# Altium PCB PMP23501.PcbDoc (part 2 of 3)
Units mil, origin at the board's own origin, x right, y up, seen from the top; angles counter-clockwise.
Board outline 4950 x 3450 mil, 4 copper layers (Top Layer, Layer 1, Layer 2, Bottom Layer), stack 70.356 mil thick; 186 components, 84 nets, 554 pads, 643 vias.
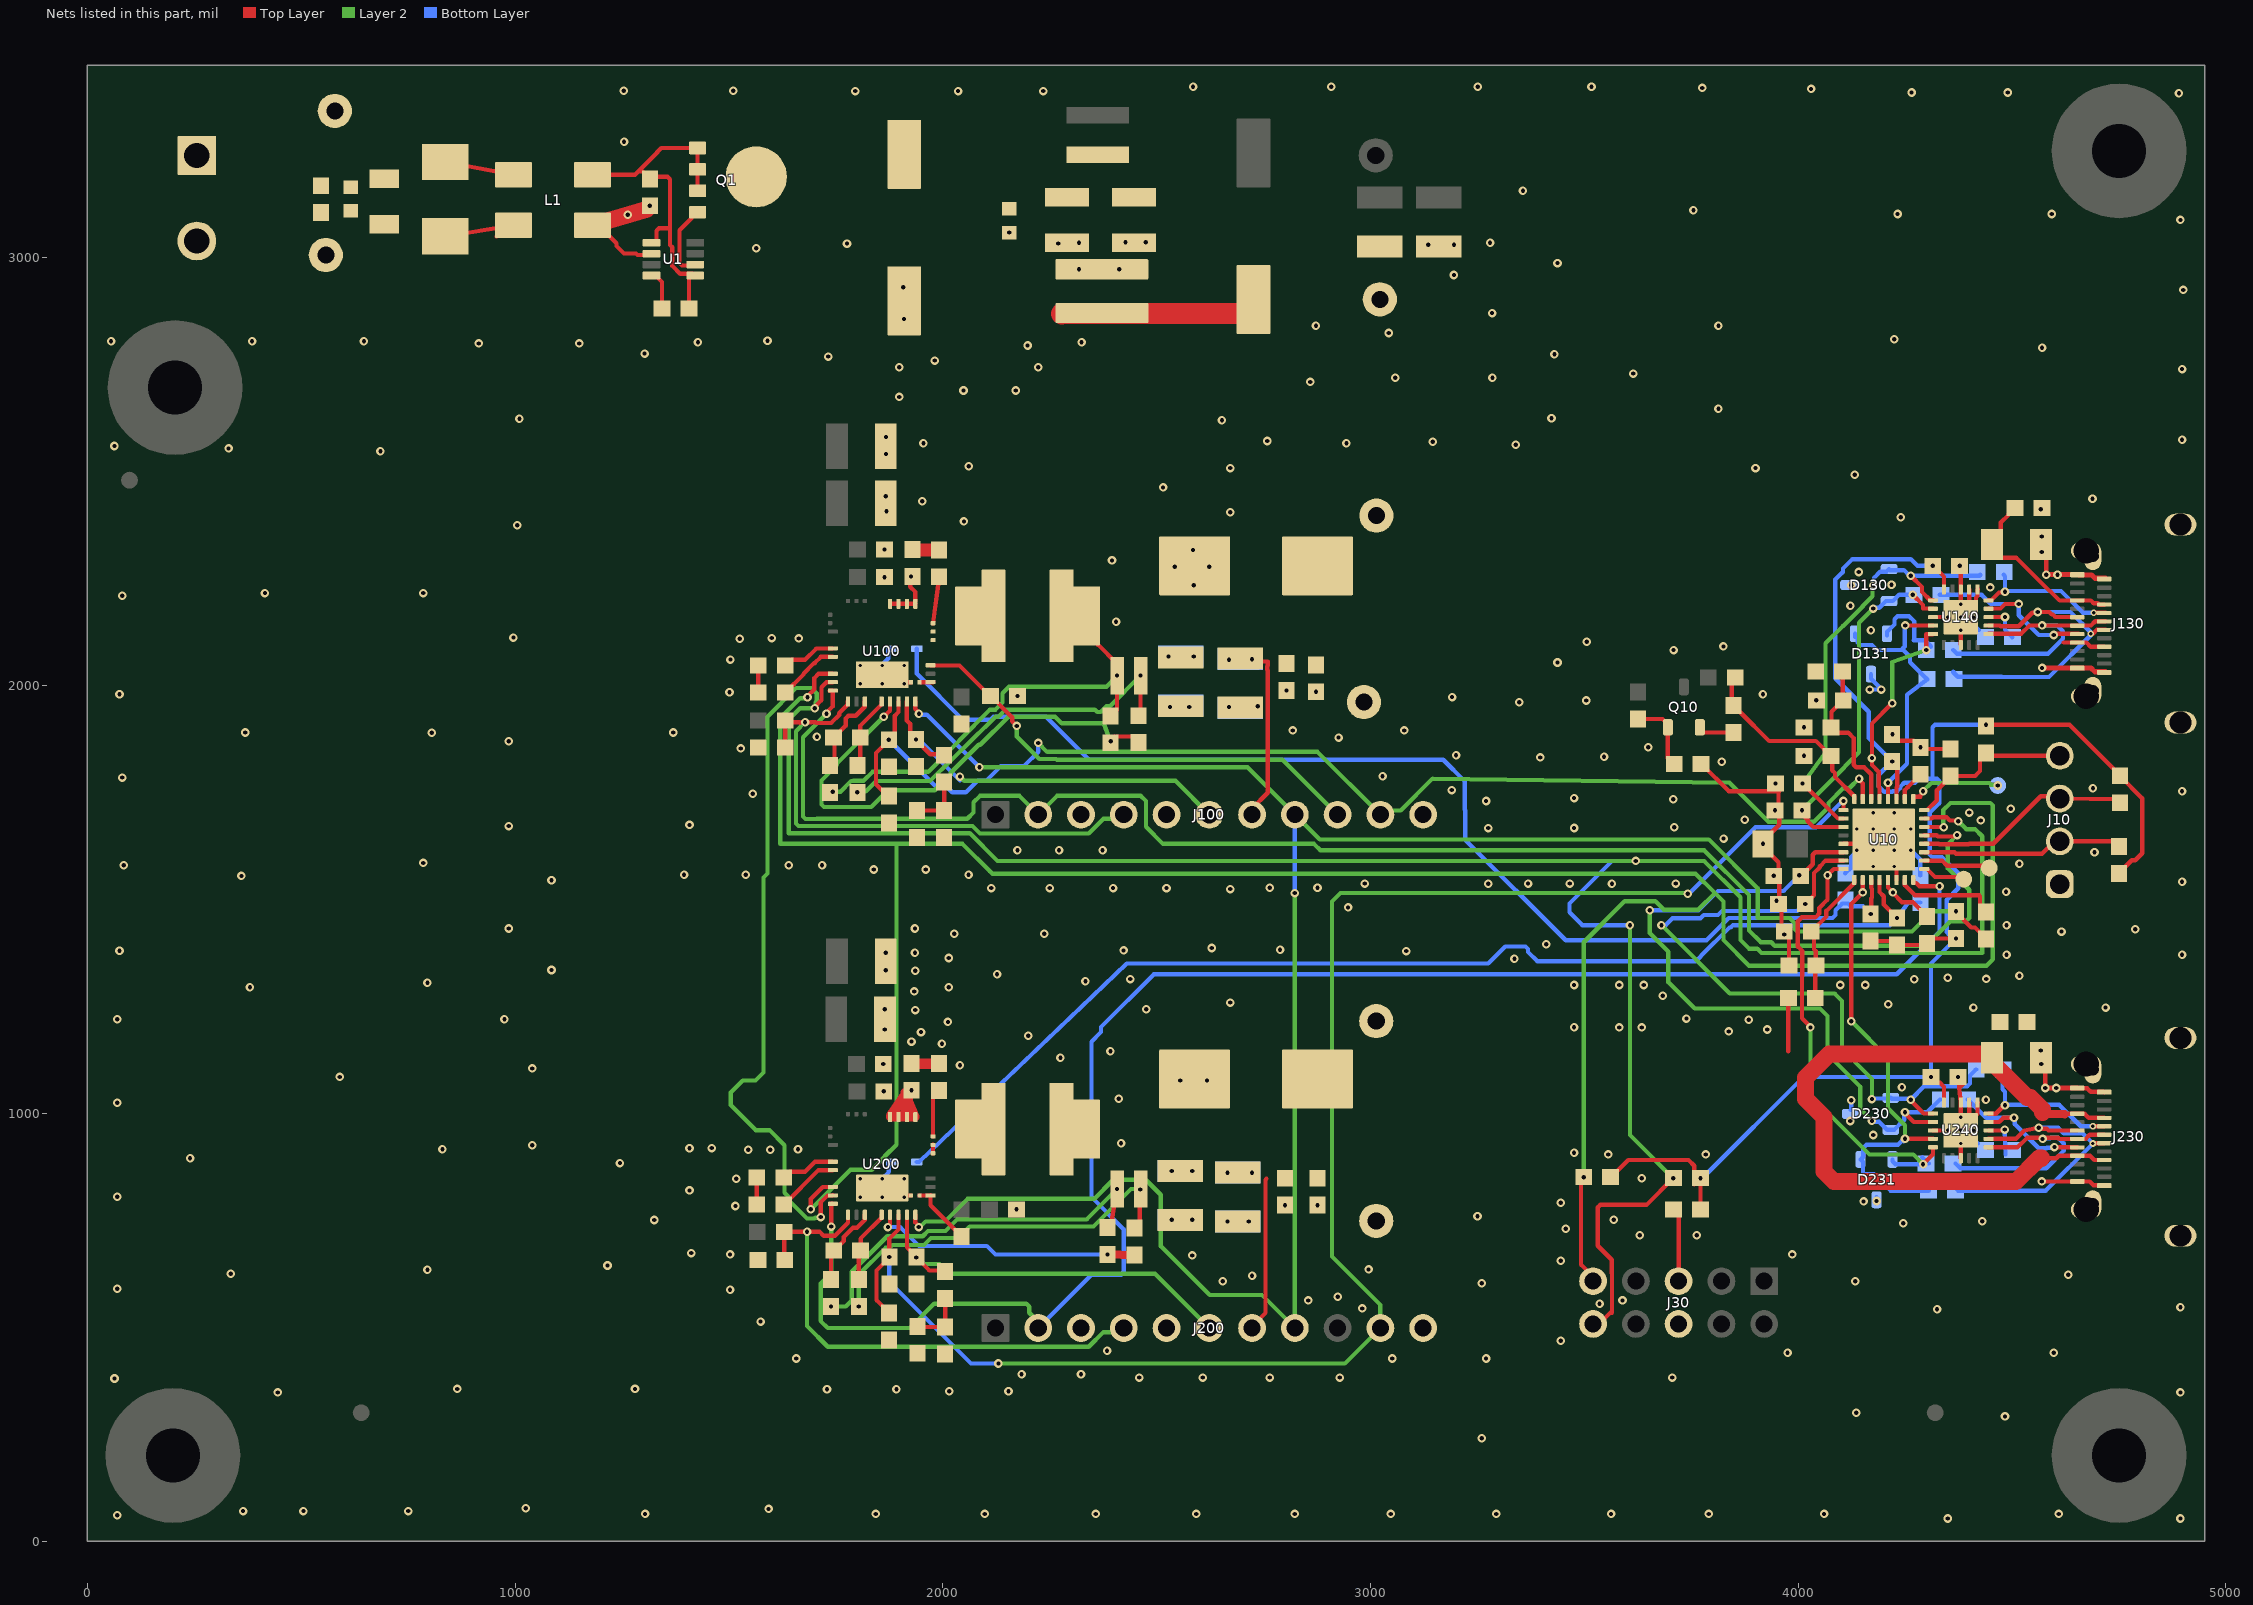
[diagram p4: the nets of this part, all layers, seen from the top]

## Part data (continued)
R106 R108 R112 R135 R136 R137 R138 R206 R208 R212 R235 R236 R237 R238: library part CMP-0025885-5, "RES, 0, 5%, 0.1 W, 0603", Manufacturer=Yageo, Power_W=100mW, Supplier Part Number 1=311-0.0GRCT-ND, TempCo="200 ppm/C", Tolerance_%=5%, Value2=0.1W, Value_Code=0000, ValueDisplayed=0
R107 R207: library part CMP-0025825-4, "RES, 51, 5%, 0.1 W, AEC-Q200 Grade 0, 0603", Manufacturer=Vishay-Dale, Power_W=100mW, Supplier Part Number 1=541-51GCT-ND, TempCo="200 ppm/C", Tolerance_%=5%, Value2=0.1W, Value_Code=51R0, ValueDisplayed=51
R109 R209: library part CMP-0022302-4, "RES, 2.00, 1%, 0.1 W, AEC-Q200 Grade 0, 0603", Manufacturer=Vishay-Dale, PartNumber=CRCW06032R00FKEA, Power_W=100mW, Supplier Part Number 1=541-2.00HHCT-ND, TempCo="100 ppm/C", Tolerance_%=1%, Value2=0.1W, Value_Code=2R00, ValueDisplayed=2.00
R111 R211: library part CMP-0015103-2, "RES, 0.008, 1%, 1 W, AEC-Q200 Grade 0, 0508", Manufacturer="Susumu Co Ltd", Power_W=1W, TempCo="25 ppm/C", Tolerance_%=1%, Value_Code=8L000, ValueDisplayed=0.008
R113 R213: library part CMP-0025832-4, "RES, 5.1 M, 5%, 0.1 W, AEC-Q200 Grade 0, 0603", Manufacturer=Vishay-Dale, Power_W=100mW, Supplier Part Number 1=541-5.1MGCT-ND, TempCo="200 ppm/C", Tolerance_%=5%, Value2=0.1W, Value_Code=5M10, ValueDisplayed=5.1M
R204: library part CMP-0022494-4, "RES, 54.9 k, 1%, 0.1 W, AEC-Q200 Grade 0, 0603", Manufacturer=Vishay-Dale, Power_W=100mW, Supplier Part Number 1=541-54.9KHCT-ND, TempCo="100 ppm/C", Tolerance_%=1%, Value2=0.1W, Value_Code=54k9, ValueDisplayed=54.9k
TP1 TP3 TP100 TP200: library part CMP-0055137-2, "Test Point, Miniature, Red, TH", Color=Red, Manufacturer="Keystone Electronics", Supplier Part Number 1=36-5000-ND
TP2 TP4 TP101 TP201: library part CMP-0055138-2, "Test Point, Miniature, Black, TH", Color=Black, Manufacturer="Keystone Electronics", Supplier Part Number 1=36-5001-ND
TP10 TP11 TP12: library part CMP-0003825-1, "1mm Test Point, SMT", Manufacturer=Any
U1: library part CMP-0090679-1, "Low IQ Reverse Battery Protection Controller", Manufacturer="Texas Instruments", Max Supply Voltage=60V, Min Supply Voltage=4V, Nominal Supply Current=80uA, Operating Temperature Range="-40°C to +150°C"
U10: library part CMP-0122052-1, "Automotive Dual-Port USB Type-C® PD Controller with 240W EPR and DisplayPortTM over USB Type-C", Manufacturer="Texas Instruments", Max Supply Voltage=32V, Min Supply Voltage=4.5V, Operating Temperature Range="-40°C to +125°C"
U100 U200: library part CMP-0123531-1, "70V, 3A, Automotive, High Efficiency CC-CV Buck Converter with I2C", Manufacturer="Texas Instruments", Max Supply Voltage=70V, Min Supply Voltage=4.5V, Operating Temperature Range="-40°C to +150°C", Output Voltage=1-24V, Switching Frequency=200-2200kHz
U140 U240: library part CMP-0035132-1, "USB Type-C® 48V EPR Port Protector: Short-to-VBUS Overvoltage and IEC ESD Protection", Manufacturer="Texas Instruments", Operating Supply Voltage=3.3V, Operating Temperature Range="-40°C to +125°C"
ZZ1: library part CMP-0003616-3
ZZ2: library part CMP-0077236-1
ZZ3: library part CMP-0077237-1
ZZ4: library part CMP-0077238-1

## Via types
v1: diameter 20, hole 10, Top Layer to Bottom Layer, tented both sides, 592 vias
v2: diameter 19.68, hole 7.87, Top Layer to Bottom Layer, tented both sides, 46 vias
v3: diameter 16, hole 8, Top Layer to Bottom Layer, tented both sides, 4 vias
v4: diameter 20/20/20/20 (per signal layer), hole 10, Top Layer to Bottom Layer, tented bottom, 1 vias

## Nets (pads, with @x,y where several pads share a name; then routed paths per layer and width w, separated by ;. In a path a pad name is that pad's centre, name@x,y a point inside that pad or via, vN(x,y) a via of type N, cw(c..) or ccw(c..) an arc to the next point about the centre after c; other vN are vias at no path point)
3.3V: C19.2 C140.1 C240.1 R12.1 R16.2 R20.2 R21.2 R22.2 R27.2 R28.2 R30.2 R31.2 R32.2 U10.27 U140.10 U240.10 | length 4088.7
  Top Layer w10: R31.2@3561.35,850.51 3562.34,850.51 3602.69,890.87 3743.2,890.87 3756.81,877.25 3756.81,861.93 R30.2@3770.51,848.23 ; R30.2@3756.81,833.55 3756.81,834.53 R30.2@3770.51,848.23 ; R32.2@3771.5,774.92 v1(3771.5,848.23) R30.2@3770.51,848.23 ; R16.2@4169.29,1403 4221.19,1403 R21.2@4230.77,1393.41 4297.14,1393.41 R22.2@4300.73,1397 4312.23,1408.5 v1(4368.59,1408.5) ; v1(4219.65,1822.76) 4231.34,1811.07 4231.34,1764.12 4229.53,1762.31 U10.27@4229.53,1734.49 ; v1(4310.31,1085) 4324.02,1071.3 4331.14,1071.3 4340.63,1061.81 U240.10@4340.63,1024.96 ; v1(4314.28,2280.06) 4315.27,2280.06 4340.63,2254.7 U140.10@4340.63,2224.96 ; v1(4438.86,1908.46) 4634.22,1908.46 4752.43,1790.25 R28.2@4752.43,1789.27 4752.43,1788.28 4804.37,1736.35 4804.37,1607.95 4788.07,1591.65 4779.66,1591.65 4749.66,1561.65 R27.2@4749.66,1560.67
  Bottom Layer w10: v1(3771.5,848.23) 3771.5,849.22 3777.35,855.08 3782.36,855.08 4012.28,1085 v1(4310.31,1085) 4310.31,1350.23 v1(4368.59,1408.5) 4365.88,1408.5 4358.01,1416.38 4354.37,1416.38 4347.09,1423.66 4347.09,1499.03 4374.09,1526.04 4374.09,1561.5 4336.32,1599.27 4313.06,1599.27 4307.2,1605.13 4307.2,1701.97 4330.39,1725.16 4330.39,1776.64 4324.54,1782.5 4314.05,1782.5 ; v1@4312.37,2281.97 v1(4314.28,2280.06) 4278.63,2280.06 4262.98,2295.71 4126.44,2295.71 4104.5,2273.77 4104.5,2265.04 4103.5,2265.04 4086.57,2248.11 4086.57,2017.11 4164.78,1938.91 4164.78,1877.63 v1(4219.65,1822.76) 4188.34,1791.45 4188.34,1764.12 4200.94,1751.53 4219.63,1751.53 4221.29,1753.19 4231.12,1753.19 4238.85,1760.92 4238.85,1764.12 4247.76,1773.03 4272.97,1773.03 4282.44,1782.5 4314.05,1782.5 ; v1(4438.86,1908.46) 4319.91,1908.46 4314.05,1902.6 4314.05,1782.5
AGND_A: C100.2 C101.2 C102.2 C104.1 NT100.2 R100.1 R104.1 R113.1 U100.17 | length 31.4
  Top Layer w10: C102.2@1873.73,1820.27 C102.2@1873.73,1822.24 ; NT100.2@1948.15,2007.87 1970.75,2007.87 1977.48,2007.87 U100.17@1977.56,2007.8
AGND_B: C200.2 C201.2 C202.2 C204.1 NT200.2 R200.1 R204.1 R213.1 U200.17 | length 152
  Top Layer w10: NT200.2@1945.66,808.02 1971.09,808.02 U200.17@1971.17,808.1 1971.17,784.89 2043.5,712.57 C204.1@2043.5,711.58
CC1_A: C17.2 D130.2 R135.1 U10.3 U140.12 | length 832.3
  Top Layer w10: C17.2@3994.95,1697.11 C17.2@3996.92,1697.11 ; C17.2@4005.03,1702.99 4022.17,1685.85 4022.17,1682.38 4035.02,1669.53 U10.3@4105.51,1669.53 ; v1(4267.76,2212.29) 4291.72,2188.32 4291.72,2180.12 U140.12@4315.04,2180.12
  Layer 2 w10: v1(4008.74,1708.5) 4142.09,1843.99 4142.09,2147.01 v1(4175.2,2180.12)
  Bottom Layer w10: v1(4175.2,2180.12) 4177.11,2182.03 4189.31,2182.03 4204.88,2197.6 4213.24,2197.6 4221.13,2197.6 4235.82,2212.29 v1(4267.76,2212.29) R135.1@4270.5,2212.29
CC1_A_C: J130.A5 R135.2 U140.4 | length 458.2
  Top Layer w10: U140.4@4444.96,2180.12 4472.63,2180.12 4483.45,2190.94 v1(4515.68,2190.94) ; v1(4597.66,2118.25) 4600.37,2118.25 4603.19,2121.06 J130.A5@4655.51,2121.06
  Bottom Layer w10: R135.2@4330.75,2212.29 4428.8,2212.29 4450.14,2190.94 v1(4515.68,2190.94) 4515.68,2164.67 4562.1,2118.25 v1(4597.66,2118.25) v1@4600.37,2118.25
CC1_B: C18.1 D230.2 R235.1 U10.6 U240.12 | length 1685.3
  Top Layer w10: v1(4002.63,1556.79) 4008.48,1556.79 4033.98,1582.29 4033.98,1604.61 4039.84,1610.47 U10.6@4105.51,1610.47 ; v1(4249.61,1002.5) 4249.61,1000.16 4270.08,979.68 U240.12@4315.04,979.68
  Layer 2 w10: v1(3652.6,1474.59) 3652.6,1421.33 3696.3,1377.63 3696.3,1306.5 3757.8,1245 4050.78,1245 4068.5,1227.28 4068.5,1138.56 4145.2,1061.86 4145.2,1009.29 v1(4172.29,982.2)
  Bottom Layer w10: v1(3652.6,1474.59) 3766.92,1474.59 3812.33,1520 3965.84,1520 v1(4002.63,1556.79) ; v1(4172.29,982.2) 4174.2,980.29 4188.9,980.29 4207.89,961.3 D230.2@4216.25,961.3 4224.12,961.3 4247.69,984.87 4247.69,1000.59 v1(4249.61,1002.5) 4301.48,1002.5 4331.46,1032.48 R235.1@4332.44,1032.48
CC1_B_C: J230.A5 R235.2 U240.4 | length 377.6
  Top Layer w10: U240.4@4444.96,979.68 4469.78,979.68 4479.39,989.29 v1(4504.46,989.29) ; v1@4598.23,921.81 4599.65,920.39 J230.A5@4652.36,920.39
  Bottom Layer w10: R235.2@4395.43,1032.48 4396.42,1032.48 4439.61,989.29 v1(4504.46,989.29) 4506.37,987.38 4506.37,974.47 4562.34,918.5 4580.15,918.5 4580.84,919.19 4597.02,919.19 v1(4598.94,921.1)
CC2_A: C15.2 D130.1 R136.1 U10.2 U140.11 | length 1023.2
  Top Layer w10: v1(4009.69,1771.1) 4010.67,1771.1 4037.37,1744.4 4038.17,1744.4 4093.28,1689.29 4105.43,1689.29 U10.2@4105.51,1689.21 ; v1(4262.99,2256.63) 4289.26,2230.37 4289.26,2218.62 4308.5,2199.37 U140.11@4315.04,2199.37
  Layer 2 w10: v1@4010.93,1770.21 4063.81,1843.99 4063.81,2099.13 4103.22,2138.54 4104.09,2138.54 4150.59,2185.04 4150.59,2185.91 4173.54,2208.87 4173.54,2232.21 v1(4175.2,2233.87)
  Bottom Layer w10: v1(4175.2,2233.87) 4177.11,2235.78 4177.11,2251.93 4191.67,2266.5 4206.34,2266.5 D130.1@4212.24,2272.4 4214.65,2269.99 4246.93,2269.99 4260.29,2256.63 v1(4262.99,2256.63) 4423.92,2256.63 4425.24,2257.95 R136.1@4425.24,2258.94
CC2_A_C: J130.B5 R136.2 U140.5 | length 344.3
  Top Layer w10: U140.5@4444.96,2199.8 4451.5,2199.8 4469.27,2217.57 4481.43,2217.57 v1(4483.35,2219.49) ; v3(4690.8,2170.28) J130.B5@4718.5,2170.28
  Bottom Layer w10: R136.2@4480.36,2258.94 4483.35,2255.95 v1(4483.35,2219.49) 4485.16,2221.3 4614.33,2221.3 4665.35,2170.28 v3(4690.8,2170.28)
CC2_B: C16.1 D230.1 R236.1 U10.7 U240.11 | length 1617.8
  Top Layer w10: v1(4016.5,1489.31) 4017.48,1489.31 4031.18,1503.01 4031.18,1503.99 4036.99,1509.8 4036.99,1561.96 4050.48,1575.46 4050.48,1577.37 4063.9,1590.79 U10.7@4105.51,1590.79 ; v1(4262.99,1031.85) 4262.99,1029.92 4293.54,999.37 U240.11@4315.04,999.37
  Layer 2 w10: v1(3680,1440) 3840,1280 4085,1280 4102.2,1262.8 4102.2,1150.09 4172.29,1080 v1(4172.29,1033.39)
  Bottom Layer w10: 3690,1440 3706,1456 3771.66,1456 3779.15,1463.48 3812.33,1463.48 3821.99,1473.13 3997.61,1473.13 4013.79,1489.31 v1(4016.5,1489.31) ; v1(4172.29,1033.39) 4173.65,1034.75 4214.89,1034.75 D230.1@4216.25,1036.11 4218.59,1033.76 4261.08,1033.76 v1(4262.99,1031.85) 4294.64,1063.5 4395.12,1063.5 4401.56,1069.94 4401.56,1088.58 4415.26,1102.28 R236.1@4416.24,1102.28
CC2_B_C: J230.B5 R236.2 U240.5 | length 386.6
  Top Layer w10: U240.5@4444.96,999.37 4445.24,999.09 4461.69,999.09 4481.42,1018.82 v1(4483.35,1018.82) ; v3(4688.78,969.61) J230.B5@4715.35,969.61
  Bottom Layer w10: R236.2@4479.23,1102.28 4477.56,1100.61 4477.56,1056.22 4483.35,1050.43 v1(4483.35,1018.82) 4484.53,1020 4610,1020 4660.39,969.61 v3(4688.78,969.61)
COMP_A: C100.1 J100.6 R101.2 U100.15 | length 940.8
  Top Layer w10: U100.15@1915.63,1962.6 1915.63,1918.65 1923.59,1910.7 1923.59,1887.43 v1(1937.29,1873.73) 1937.29,1872.75 1970.61,1839.42 R101.2@2003.27,1839.42
  Layer 2 w10: v1(2039.96,1787.26) 2040.11,1787.26 2049.93,1777.44 2543.73,1777.44 J100.6@2622.99,1698.19
  Bottom Layer w10: v1(1937.29,1873.73) 1939.2,1871.82 1946.38,1871.82 v1@2040,1778.2
COMP_B: C200.1 J200.6 R201.2 U200.15 | length 943.3
  Top Layer w10: U200.15@1916.06,762.83 1916.06,686.87 1938.02,664.9 C200.1@1938.02,663.92 v1(1938.02,663) 1938.02,662.93 1968.53,632.42 2002.87,632.42 R201.2@2005.37,629.92
  Layer 2 w10: v1(1938.02,663) 1940.73,663 1956.13,647.6 1992.4,647.6 2015,625 2496,625 J200.6@2623,498
D+_A: D131.2 R137.1 U10.29 U140.15 | length 675.6
  Top Layer w10: U10.29@4190.16,1734.49 4190.16,1761.3 4188.34,1763.11 4188.34,1798.37 4172.29,1814.42 v1(4172.29,1830.46) 4172.29,1911.61 v1(4219.65,1958.98) ; v1(4299.25,2083.11) 4299.25,2120.02 4299.59,2120.35 4314.76,2120.35 U140.15@4315.04,2120.63
  Layer 2 w10: v1(4219.65,1958.98) 4219.65,2055.16 v1(4299.25,2083.11)
  Bottom Layer w10: D131.2@4207.4,2117.24 4207.4,2125.61 4224.81,2143.02 4224.81,2155.18 4231.88,2162.25 4258.91,2162.25 4271.5,2149.65 4271.5,2107.01 4270.33,2105.84 4270.43,2105.75 4295.33,2105.75 4298.27,2102.81 4299.25,2102.81 4310,2092.06 R137.1@4310,2091.08
D+_A_C: J130.A6 J130.B6 R137.2 U140.1 | length 633.5
  Top Layer w10: U140.1@4444.96,2121.06 4521.14,2121.06 4540.83,2140.75 v1(4570,2140.75) 4684.67,2140.75 4694.43,2150.51 4718.43,2150.51 J130.B6@4718.5,2150.59
  Bottom Layer w10: R137.2@4362.24,2083.11 4371.07,2074.28 4584.1,2074.28 4619.16,2109.34 4619.16,2127.15 4605.57,2140.75 v1(4570,2140.75)
D+_B: D231.2 R237.1 U10.8 U240.15 | length 1097.2
  Top Layer w10: v1(4028.45,1200.69) 4028.45,1202.3 4008.62,1222.13 4008.62,1321.3 4009.37,1322.05 4009.37,1379.35 3999.04,1389.68 3999.04,1448.94 4008.23,1458.13 4039.97,1458.13 4049.16,1467.32 4049.16,1480.17 4068.5,1499.51 v1(4068.5,1556.79) 4082.81,1571.1 U10.8@4105.51,1571.1 ; v1(4291.81,881.02) 4315.04,904.25 U240.15@4315.04,920.63
  Layer 2 w10: v1(4028.45,1200.69) 4028.45,1041.79 4166.48,903.76 4269.07,903.76 v1(4291.81,881.02)
  Bottom Layer w10: D231.2@4220.49,892.19 4220.49,887.77 4227.23,881.02 v1(4291.81,881.02) ; R237.1@4290.14,897.4 4290.14,896.41 4303.84,882.71 R237.1@4304.83,882.71
D+_B_C: J230.A6 J230.B6 R237.2 U240.1 | length 632.1
  Top Layer w10: U240.1@4444.96,920.63 4512.68,920.63 4534.65,942.6 4607.84,942.6 4610.37,940.08 J230.A6@4652.36,940.08 4652.44,940.16 4671.87,940.16 4681.64,949.92 J230.B6@4715.35,949.92
  Bottom Layer w10: R237.2@4367.82,882.71 4379.08,871.44 4579.68,871.44 4620.44,912.2 4620.44,930.01 4607.84,942.6 4590.03,942.6 4589.34,941.91 4573.16,941.91 v1(4571.25,940)
D-_A: D131.1 R138.1 U10.28 U140.14 | length 686.4
  Top Layer w10: U10.28@4209.84,1734.49 v1(4209.84,1773.03) ; v1(4250,2140.75) U140.14@4315.04,2140.75
  Bottom Layer w10: D131.1@4132.6,2113.86 D131.1@4132.6,2121.24 4138.5,2115.34 4138.5,2100.67 4144.36,2094.82 4172.4,2094.82 4184.11,2083.11 4240.37,2083.11 4244.6,2087.34 ; v1(4209.84,1773.03) 4254.1,1817.29 4254.1,1978.14 R138.1@4302.02,2014.44 ; v1@4251.91,2138.83 v1(4250,2140.75) 4248.83,2139.58 4248.83,2091.57 4244.6,2087.34 ; R138.1@4300.94,2015.87 4299.96,2015.87 4261.08,2054.75 4261.08,2067.53 4244.6,2084 4244.6,2087.34
D-_A_C: J130.A7 J130.B7 R138.2 U140.2 | length 789.2
  Top Layer w10: U140.2@4444.96,2140.75 4471.77,2140.75 4473.59,2138.93 4515.68,2138.93 4546.9,2170.16 4558.09,2170.16 v1(4560,2172.07) 4586.74,2172.07 4592.65,2166.16 4595.36,2166.16 4601.09,2160.43 J130.A7@4655.51,2160.43 ; v3@4687.24,2121.06 4688.87,2121.06 4698.63,2130.83 4718.43,2130.83 J130.B7@4718.5,2130.91
  Bottom Layer w10: R138.2@4364.52,2030.02 4362.32,2032.22 4362.32,2031.24 4373.07,2020.49 4475.66,2020.49 4476.31,2019.84 4586.02,2019.84 4687.24,2121.06 4636.24,2172.07 v1(4560,2172.07)
  other v3: 4684,2121.06
D-_B: D231.1 R238.1 U10.10 U240.14 | length 1084.2
  Top Layer w10: v1(4123.7,1215.51) 4123.7,1489.31 v1(4150.79,1516.4) U10.10@4150.79,1545.51 ; v1(4249.61,940.32) U240.14@4315.04,940.32
  Layer 2 w10: v1(4123.7,1215.51) 4209.84,1129.37 4209.84,1011.86 4249.61,972.09 v1(4249.61,940.32)
  Bottom Layer w10: v1@4246.73,934.73 4249.61,937.61 v1(4249.61,940.32) 4246.9,940.32 4233.19,926.6 4159.32,926.6 4151.94,919.23 4151.94,898.44 D231.1@4145.69,892.19 4151.23,886.65 4151.23,857.58 4177.16,857.58 4215.57,819.17 R238.1@4304.83,819.17 ; R238.1@4309.48,828.14 R238.1@4309.48,829.12
D-_B_C: J230.A7 J230.B7 R238.2 U240.2 | length 760.6
  Top Layer w10: U240.2@4444.96,940.32 4509.03,940.32 4528.48,959.76 v1(4562.34,966) 4564.24,964.1 4580.66,964.1 4585,959.76 J230.A7@4652.36,959.76 ; v3(4688.78,929.49) 4689.45,930.16 4715.28,930.16 J230.B7@4715.35,930.24
  Bottom Layer w10: R238.2@4364.6,828.14 4373.57,819.17 4578.46,819.17 v3(4688.78,929.49) 4665.16,953.11 4620.74,953.11 4607.85,966 v1(4562.34,966)
EMIGND: C0.2 C1.2 C2.2 D1.1 J1.2 L1.2 TP2.1 | length 212.1
  Top Layer w10: D1.1@836.61,3050.22 L1.2@996.06,3076.21 982.28,3076.21 L1.2@956.3,3050.22
EN/UVLO_A: J100.4 R100.2 R102.1 U100.9 | length 1281.8
  Top Layer w10: R100.2@1631.56,1854.74 R102.1@1631.56,1918.65 1635.65,1914.56 1664.11,1914.56 1666.11,1912.56 1666.72,1912.56 1668.72,1914.56 v1(1677.98,1914.56) 1702.78,1914.56 1704.78,1912.56 1738.84,1912.56 1757.61,1931.33 1757.61,1935.64 1777.84,1955.87 U100.9@1777.84,1962.6
  Layer 2 w10: v1(1677.98,1914.56) 1656.5,1893.08 1656.5,1677.65 1662.65,1671.5 2069.59,1671.5 2086.89,1654.21 2341.21,1654.21 2375.51,1688.51 2413.31,1688.51 J100.4@2422.99,1698.19
EN/UVLO_B: J200.4 R200.2 R202.1 U200.9 | length 1249.8
  Top Layer w10: R200.2@1630.48,657.47 1629.24,658.71 R202.1@1629.24,722.4 1630.13,723.29 v1(1682.54,723.29) 1711.75,723.29 1721.29,713.75 1747.8,713.75 1778.18,744.14 1778.18,762.75 U200.9@1778.26,762.83
  Layer 2 w10: v1(1682.54,723.29) 1682.54,502.92 1682.31,502.69 1730.98,454.02 2341.22,454.02 2375.52,488.32 2413.32,488.32 J200.4@2423,498
GND: C3.2 C5.2 C6.2 C7.2 C8.2 C10.2 C11.2 C12.2 C13.2 C14.2 C15.1 C16.2 C17.1 C18.2 C19.1 C20.2 C21.1 C103.2 C105.2 C106.2 C107.2 C108.2 C109.2 C113.2 C114.2 C115.2 C116.2 C117.2 C118.2 C119.2 C130.2 C131.2 C140.2 C141.2 C203.2 C205.2 C206.2 C207.2 C208.2 C209.2 C213.2 C214.2 C215.2 C216.2 C217.2 C218.2 C219.2 C230.2 C231.2 C240.2 C241.2 D130.3 D131.3 D230.3 D231.3 J10.1 J30.6 J100.3 J100.5 J100.11 J130.1 J130.2 J130.3 J130.4 J130.A1 J130.A12 J130.B1 J130.B12 J200.3 J200.5 J200.11 J230.1 J230.2 J230.3 J230.4 J230.A1 J230.A12 J230.B1 J230.B12 L1.3 NT100.1 NT200.1 R1.2 R11.2 R15.2 R19.1 R26.2 R105.2 R109.2 R205.2 R209.2 TP4.1 TP101.1 TP201.1 U1.2 U10.5 U10.14 U10.33 U100.23 U100.24 U100.25 U100.26 U100.30 U140.6 U140.7 U140.8 U140.13 U140.18 U140.21 U200.23 U200.24 U200.25 U200.26 U200.30 U240.6 U240.7 U240.8 U240.13 U240.18 U240.21 | length 3591.4
  Top Layer w10: L1.3@1181.1,3076.21 1194.88,3076.21 1237.06,3034.03 1237.06,3027.65 1254.71,3010 1282.7,3010 1285.97,3006.73 U1.2@1326.17,3006.73 ; C3.2@1300.33,3107.05 1301.32,3107.05 1315.02,3120.75 v1(1315.02,3121.74) ; U200.26@1876.26,998.33 1876.68,997.91 U200.26@1876.68,991.17 ; U100.26@1876.68,2191.17 U100.25@1896.37,2191.17 U100.24@1916.06,2191.17 U100.23@1935.74,2191.17 ; 1888.55,991.17 1892.2,999.69 R209.2@1912.65,1046.86 ; U200.25@1896.37,991.17 1896.37,997.91 1896.45,997.98 1899.84,997.98 1905.7,1003.84 ; 1905.7,1019.61 1905.7,1003.84 ; v2(1910.15,804.17) 1914.01,808.02 NT200.1@1925.66,808.02 ; v2(1910.15,2004.17) 1913.78,2007.8 NT100.1@1925.4,2007.8 ; U200.24@1916.06,991.17 1916.06,997.91 1915.98,997.98 1911.56,997.98 1905.7,1003.84 ; R209.2@1920.76,1034.64 R209.2@1925.71,1046.17 ; 1923.59,2233.77 1923.59,2231.07 1935.74,2218.92 U100.23@1935.74,2197.98 ; R209.2@1925.71,1034.64 R209.2@1925.71,1046.17 ; R209.2@1926.7,1046.17 R209.2@1925.71,1046.17 ; U200.23@1935.74,991.17 U200.23@1935.66,991.25 ; R26.2@3772.9,1816.64 3773.89,1816.64 3837.34,1753.19 C15.1@3955.42,1753.19 ; 3953.85,1750.83 3953.85,1702.99 3955.38,1701.45 3955.38,1674.56 3917.48,1636.66 v1(3917.48,1630.16) 3917.48,1623.66 3954.01,1587.14 3954.01,1558.17 3955.38,1556.79 3955.38,1505.68 3961.06,1500 3961.06,1464.58 C11.2@3959.69,1419.62 ; C11.2@3972.33,1425.48 3978.19,1419.62 R15.2@3978.19,1345.52 ; C21.1@4008.62,1822.11 C21.1@4009.6,1822.11 ; U10.5@4105.51,1630.16 4190.16,1630.16 U10.33@4200,1640 v2(4224.8,1615.2) 4229.53,1610.47 U10.14@4229.53,1545.51 ; C19.1@4219.65,1885.75 4219.65,1884.77 4233.35,1871.06 4270.29,1871.06 4271.11,1870.24 4272.09,1870.24 4285.8,1856.54 v1(4285.8,1855.56) ; C20.2@4275.71,1844.65 C20.2@4275.71,1844.94 ; C20.2@4275.71,1848.59 C20.2@4275.71,1844.94 ; C20.2@4282.52,1851.75 C20.2@4275.71,1844.94 ; C20.2@4285.8,1851.75 R19.1@4356.44,1851.75 ; U240.13@4315.04,960 v2(4349.49,960) ; U140.13@4315.04,2160.43 U140.21@4349.49,2160.43 ; v1(4373.31,1085) U240.8@4380,1024.96 v2(4380,990.51) 4394.84,990.51 4399.69,995.35 U240.7@4399.69,1024.96 ; U240.18@4380,895.04 v2(4380,929.49) ; v2(4380,960) 4419.09,999.09 4419.09,1024.68 U240.6@4419.37,1024.96 ; 4380,1062.44 C240.2@4387.56,1070 ; U140.18@4380,2095.47 U140.21@4380,2129.92 ; U140.21@4380,2160.43 4399.69,2180.12 U140.21@4399.69,2189.96 ; U140.21@4380,2190.94 U140.8@4380,2224.96 4380,2265.92 C140.2@4385.51,2271.43 ; U140.7@4399.69,2225.39 U140.21@4399.69,2189.96 ; U140.6@4419.37,2225.39 4419.09,2225.12 4419.09,2209.37 4415.35,2205.63 4415.35,2195.79 4409.53,2189.96 U140.21@4399.69,2189.96 ; C131.2@4561.55,2330.92 4580,2312.46 v1(4580,2258.94) v1@4580.45,2259.39 ; C231.2@4567.09,1130 C231.2@4585,1112.09 ; v1(4569.06,840.67) J230.A1@4652.36,840.67 4681.46,840.67 4690.39,831.73 4714.45,831.73 J230.B12@4715.35,830.83 ; C231.2@4577.16,1106.23 v1(4577.16,1059.17) 4590.86,1059.17 ; J230.A12@4652.36,1059.17 4653.27,1058.27 4675.68,1058.27 4683.71,1050.24 4714.45,1050.24 J230.B1@4715.35,1049.33 ; J130.A12@4655.06,2259.39 4655.51,2259.84 J130.A12@4656.42,2258.94 ; J130.B12@4717.6,2032.4 J130.B12@4718.5,2031.5 ; J130.B1@4717.6,2250.91 J130.B1@4718.5,2250
  Top Layer w12: v1(4570,2041.34) 4684.5,2041.34 4693.44,2032.4 J130.B12@4717.6,2032.4 ; v1(4577.16,1059.17) J230.A12@4652.36,1059.17 ; v1@4580.45,2259.39 v1(4606.14,2259.39) J130.A12@4655.06,2259.39 ; J130.A12@4656.42,2258.94 4685.64,2258.94 4693.67,2250.91 J130.B1@4717.6,2250.91
  Top Layer w20: U200.26@1876.68,991.17 U200.25@1896.37,991.17 U200.24@1916.06,991.17 U200.23@1935.74,991.17 ; U200.26@1876.68,994.54 R209.2@1912.65,1046.86 ; 1905.7,1017.49 1921.18,1003.93 ; R209.2@1911.56,1049.5 U200.23@1935.66,991.25
  Top Layer w40: L1.3@1181.1,3076.21 C3.2@1308.17,3113.9
  Bottom Layer w10: v2@1858.04,2046.61 1858.04,2049.23 1872.41,2063.6 1872.41,2083.19 1875.28,2086.06 R105.2@1880.59,2086.06 ; v2(1858.46,846.84) 1858.46,847.75 1873.83,863.13 1873.83,883.13 1876.7,886 R205.2@1880.87,886 ; C13.2@4110,1561.5 4123.7,1575.2 4123.7,1599.27 4137.01,1612.58 v2(4137.01,1615.2) ; D230.3@4123.03,1007.8 4123.7,1008.46 v1(4123.7,1030.43) ; v1(4167.05,1990.67) v1(4193.9,1990.67) 4193.9,1991.97 4170,2015.87 D131.3@4170,2026.69 ; D231.3@4183.09,803.51 4183.09,796.91 D231.3@4185,795 ; v2(4262.99,1615.2) 4285.51,1592.68 C14.2@4285.51,1555.99 ; v2(4410.51,960) 4410.51,938.62 C241.2@4419.64,929.49 ; v2@4410.51,2160.43 4411.69,2159.25 4411.69,2140.67 C141.2@4422.44,2129.92
  other v1: 4349.49,52.62 4893.5,52.62 70,60 1303.82,63.36 1842.95,63.36 2098.11,63.36 2357.39,63.36 2592.75,63.36 2822.99,63.36 3046.93,63.36 3294.13,63.36 3562.34,63.36 3790.65,63.36 4060.25,63.36 4608.95,63.36 363.98,70 505,70 750,70 1592.66,75 1025,76.45 3260,240 4483.35,291.3 4135.43,300 445,347.38 4893.5,347.38 2015,350 2153.53,350 1729.17,355 1891.53,355 865,355.61 1280.27,355.61 63.36,380 2459.32,382.08 2607.95,382.08 2764.58,382.08 2928.13,382.08 3705.27,382.08 2184.02,390 2322.99,390 1657.38,426.73 3050.56,426.73 3270.14,426.73 3975,440 4597.08,440 2384.02,445 3445,468.52 1573.86,513.05 4324.63,542.06 2980.37,543.82 4893.5,546.48 3535.36,555 2854.19,562.41 3589.12,562.41 2923,571.18 1502.45,587.71 70,590 3260,602.37 2654.19,607.5 4133.05,607.5 2723,620.07 4631.16,622.55 335,625 795,634.17 2995.4,635 1216.01,644.15 3445,655 2583.4,667.7 1502.45,669.97 3986.13,670 1411.58,673.27 3629.35,715 3762.72,715 3456.26,730 4245.7,743.14 2665.47,747.08 2715,747.08 4430.24,747.83 1325.33,750.5 2535,750.91 2583.4,751.02 3568.78,751.02 3250,759.15 2172.26,775.56 1514.98,783.28 2799.83,785.24 2875.98,785.24 3445,791.18 4152.79,793.97 4183,795 70,805 1407.69,819.72 1516.77,846.84 3633.99,848.23 1245,883.68 240,895 3556.04,903.76 3783.99,903.76 3475.74,907.91 1545.35,914.94 1596.61,914.94 830,915.86 1661.33,915.86 1407.69,918.02 1460,918.68 1040,925.47 2416.79,930.3 4175.57,949.22 4121.42,982 70,1025 4438.86,1031.85 2411.27,1034 1861.92,1051.28 1926.7,1053.79 4603.28,1059.17 4242.38,1061.08 2555,1076.6 2617.7,1076.6 590.2,1085 1040,1105 2040,1112.56 4567.96,1115.08 1860.85,1115.52 2275,1130 2391.8,1145 4567.09,1146.86 1997.89,1162.64 1926.7,1167.65 2199.49,1181.07 1948.98,1190 3837.34,1191.34 1864.39,1195.94 3927.37,1195.94 3581.33,1200.69 3633.99,1200.69 3475.74,1201.52 2011.98,1213.74 3883.99,1218.5 70,1220 975,1220 3738.53,1221.6 1935.4,1241.32 1864.39,1243.3 2475.52,1243.3 4409.53,1247.22 4718.5,1247.22 4210.41,1254.72 2672.28,1258.84 3683.28,1275 1933.42,1285 380,1295 2013.75,1295 3475.74,1300 3581.33,1300 3638.61,1300 4098.3,1300 4156.48,1300 795,1305 2333.4,1308.5 4271.5,1313.27 2438.04,1313.9 4439.61,1314.17 4349.49,1316.71 4517.16,1321.3 2126.72,1325 1935.4,1333.34 1866.84,1334.5 1085,1335 3336.48,1361.5 2013.75,1363.17 4487.08,1370.72 4897.39,1370.72 1866.62,1375.5 1934.74,1375.5 3083.64,1379.22 75,1380 2422.61,1380.78 2788.38,1382.64 2628.85,1386.51 3411.1,1395.14 3967.23,1418 2026.45,1420 2236.98,1420 4615.44,1425 4788.07,1430.37 985,1432.14 1934.74,1432.14 4487.08,1440 2947.39,1481.42 3949.22,1496.99 4485.91,1517.75 2672.28,1524.35 2113.27,1526.61 2250,1526.61 2397.91,1526.61 2522.99,1526.61 2764.58,1527.18 2875.98,1527.18 2986.67,1537.14 3275,1536.73 3368.21,1537.14 3466,1537.14 3564.33,1536.73 3713.41,1537.14 4897.39,1541.67 1085,1545 360,1555 3942.81,1555.1 1394.92,1557.81 1538.99,1557.81 2060.17,1557.81 1838.45,1570 1959.86,1570 85,1580 1639.46,1580 1717.57,1580 4517.16,1583.36 785,1585.31 4692.61,1610.47 2174.5,1615.2 2271.83,1615.2 2373.39,1615.2 3825.45,1642.32 3275,1666.81 3475.74,1666.99 3710,1668.74 985,1671.5 1407.69,1674.25 4426.48,1684.79 3875,1686.16 4399.69,1703.23 3945.75,1708.5 4496.93,1711.85 3270.14,1730.12 3707.52,1734.51 3475.74,1736.98 1555.25,1747.17 4897.39,1752.91 3190,1755.83 4688.87,1759.78 3946.69,1771.1 81.45,1785 3028.12,1788.27 3821.31,1822.11 3397.09,1832.04 3545.91,1833.4 4013.49,1835.85 3200,1837.16 1527.75,1853.13 3649.4,1855.56 985,1870.14 2925.21,1878.56 1705.72,1880.11 4220.57,1886.5 368.98,1890.29 805,1890 1369.67,1890.29 2817.86,1895.15 3078.76,1895.15 4013.49,1902.49 2531,1950 2576,1950 2669,1950 2736,1951.62 3347.51,1961.02 3504.41,1965.09 4042.31,1965.63 3190.65,1973.19 2174.5,1975.74 75,1980 3917.38,1979.71 1501.23,1984.35 2872.25,1985.48 2803.35,1988.43 3437.05,2054 1503.43,2060.83 3708.41,2082.99 3825,2091.54 3505.39,2102.81 1525.29,2109.83 1662.91,2110.28 1600.07,2111.07 996.06,2112.2 4170,2129.28 2405.08,2149.04 4122,2186.86 81.45,2210 415,2216.25 785,2216.25 4449,2229.59 2586.81,2234.45 4123.7,2234.45 4218.01,2235.78 1863.59,2253.32 1925.4,2255.1 4141.44,2265.57 2542,2278 2622.99,2278 4377.27,2280.06 2395.53,2292.62 4569.06,2312.46 2585,2317 1863.59,2318.1 4569.06,2348.8 1005,2375 2049.3,2383.89 4239.63,2393.67 2672.28,2405.51 1868.19,2407.9 4567.09,2412.04 1951.68,2431 4687.92,2436.96 1866.62,2442.58 2515,2463.37 4131.79,2493.19 2672.28,2508.53 3900,2508.53 2060.88,2512.94 1867.17,2541.24 685,2547.8 330,2554.42 63.21,2560.21 3339.37,2562.99 1954.67,2566.75 2943.53,2566.75 3145.27,2569.88 2758.64,2571.85 4897.39,2575 1867.17,2581.05 2652.5,2620.08 1010,2624.17 3423.07,2624.92 3813.29,2647.48 1897.82,2675 2048.29,2690 2170.48,2690 2859.31,2710 3058,2720 3285,2720 3614.27,2729.48 4897.39,2740 1897.82,2744.04 2222.99,2744.04 1981.19,2760 1731.87,2769.24 3430,2775 1302.66,2776.32 4570,2790 2198.05,2795.13 915,2800 1150,2800 1427.48,2802.5 2324.31,2802.5 55.3,2805.2 385,2805.2 646.52,2805.2 1590,2806.04 4224.13,2810 3042.47,2824.35 2872.25,2841.26 3813.29,2841.26 1909.24,2856.98 3284.09,2870.89 4900,2925 1907.76,2931.5 3195,2960 2318.57,2973.25 2412.52,2973.25 3437.05,2987.94 1563.72,3022.8 3135,3030.82 3195,3030.82 1775.98,3033.39 2269.68,3033.39 2318.57,3035.43 3279.39,3035.43 2426.94,3036.42 2474.41,3036.42 2155.51,3059.21 4893.5,3088.83 1263.54,3100.66 4232.1,3102.61 4592.65,3102.61 3755,3111.63 3356.34,3157.17 1254.71,3271.74 4890,3385 4265,3386.64 4490,3386.64 1795,3390 2035.53,3390 2235,3390 1254.02,3390.55 1510,3390.55 4030,3395 3775.32,3397.39 2585,3400 2908.04,3400 3250.39,3400 3516.53,3400
  other v2: 1806.8,804.17 1858.46,804.17 1806.8,846.84 1910.15,846.84 4175.2,1577.01 4224.8,1577.01 4175.2,1615.2 4137.01,1664.8 4175.2,1664.8 4224.8,1664.8 4262.99,1664.8 4175.2,1702.99 4224.8,1702.99 1806.8,2004.17 1858.46,2004.17 1806.8,2046.84 1858.46,2046.84 1910.15,2046.84 4380,2129.49 4349.49,2160 4380,2160 4410.51,2160 4380,2190.51
I2CtoDCDC-clk: J30.9 R31.1 U10.22 U100.6 U200.6 | length 6306.2
  Top Layer w10: v1(1683.58,1972.63) 1683.58,1975.34 1699.64,1991.39 1699.64,2017.93 1709.27,2027.56 1742.41,2027.56 1742.33,2027.48 1728.23,2027.48 ; v1(1691.22,775.43) 1691.22,799.84 1719.16,827.79 U200.6@1742.83,827.79 ; v1(3498.36,850.51) 3491.81,843.96 3491.81,646.14 3520.31,617.64 J30.9@3520.31,607.5 ; U10.22@4294.49,1669.53 4294.57,1669.45 4339.13,1669.45 v1(4339.84,1668.74)
  Layer 2 w10: v1(1683.58,1972.63) 1681.67,1970.72 1666.52,1970.72 1620,1924.19 1620,1630 1891.53,1630 ; v1(1691.22,775.43) 1783.97,868.18 1834.11,868.18 1864.39,898.46 1864.39,899.45 1891.53,926.59 1891.53,1630 ; v1(3498.36,850.51) 3498.36,1400 3594.45,1496.09 3665.65,1496.09 3685.56,1476.18 3766.19,1476.18 3805,1515 ; v1(4339.84,1668.74) 4339.13,1669.45 4339.13,1708.9 4355.87,1725.64 4449.14,1725.64 4455,1719.78 4455,1360 4440,1345 3885,1345 3825,1405 3825,1495 3805,1515 ; 1891.53,1630 2045.94,1630 2110,1565.94 2110,1565.86 2115.86,1560 3760,1560 3805,1515
I2CtoDCDC-data: J30.10 R30.1 U10.23 U100.7 U200.7 | length 6949.8
  Top Layer w10: v1(1700.35,1947.19) 1700.35,1949.9 1716.4,1965.95 1716.4,1995.97 1728.23,2007.8 1742.33,2007.8 U100.7@1742.41,2007.87 ; v1(1714.28,757.49) 1714.28,791.72 1730.59,808.02 1742.75,808.02 U200.7@1742.83,808.1 ; J30.10@3520.31,507.5 3534.59,507.5 3561.03,533.93 3564.29,533.93 3564.29,625.72 3563.86,626.15 3563.86,657.55 3531.06,690.35 3531.06,780.11 3536.92,785.97 3645.26,785.97 v1(3707.52,848.23) R30.1@3708.5,848.23 ; U10.23@4294.49,1689.21 4294.57,1689.29 4311.93,1689.29 4315.04,1692.4 4346.59,1692.4 4354.19,1684.79 4372.18,1684.79 v1(4374.09,1682.88)
  Layer 2 w10: v1(1714.28,757.49) 1712.37,755.57 1701.77,755.57 1700.12,753.93 1682.31,753.93 1640,796.24 1640,804.17 1630,814.17 1630,925.47 1594.76,960.71 1562.78,960.71 1503.99,1019.5 1503.99,1048.5 1532.24,1076.75 1561.75,1076.75 1580.55,1095.55 1580.55,1551.46 1590,1560.91 1590,1927.17 1656.96,1994.13 1692.49,1994.13 1705.08,1981.54 1705.08,1963.72 1702.26,1960.9 1702.26,1949.11 v1(1700.35,1947.19) 1666.33,1947.19 1640,1920.86 1640,1655 2062.76,1655 2127.76,1590 v1(3620,1590) 3780,1590 3865,1505 3865,1405 3885,1385 3904.19,1385 3914.19,1375 4430,1375 4430,1647.78 4413.41,1664.38 4392.6,1664.38 v1(4374.09,1682.88) ; v1(3606.53,1440) 3606.53,949.22 v1(3707.52,848.23)
  Bottom Layer w10: v1(3606.53,1440) 3495,1440 3465,1470 3465,1490.67 3564.33,1590 v1(3620,1590) ; v1@4372.18,1684.79 v1(4374.09,1682.88)
I2CtoHOST-clk: J10.2 R27.1 U10.19 | length 473.7
  Top Layer w10: U10.19@4294.49,1610.47 4365.06,1610.47 4368.59,1606.95 4371.29,1606.95 4569.85,1606.95 4598.75,1635.85 J10.2@4611.52,1635.85 4737.47,1635.85 R27.1@4749.66,1623.66
I2CtoHOST-data: J10.3 R28.1 U10.20 | length 504.3
  Top Layer w10: U10.20@4294.49,1630.16 4328.23,1630.16 4329.4,1628.99 4398.52,1628.99 4399.69,1630.16 4456.06,1630.16 4567.09,1741.19 4606.18,1741.19 J10.3@4611.52,1735.85 R28.1@4749.66,1734.49
IMON_A: C102.1 J100.10 R104.2 U10.31 U100.14 | length 2880.3
  Top Layer w10: R104.2@1872.83,1740.9 1871.84,1740.9 1843.53,1769.21 1843.53,1842.24 1873.73,1872.44 v1(1873.73,1873.42) 1887.43,1887.12 1887.43,1929.29 1896.29,1938.15 1896.29,1962.75 U100.14@1896.37,1962.83 ; C102.1@1873.73,1861.61 C102.1@1875.68,1859.67 ; v1(4142.09,1782.5) 4142.09,1779.79 4150.79,1771.1 U10.31@4150.79,1734.49
  Layer 2 w10: v1(2222.99,1865.96) 2243.82,1845.13 2876.05,1845.13 J100.10@3022.99,1698.19 3032.67,1707.86 3070.47,1707.86 3145.11,1782.5 3839.06,1773.03 3930.6,1681.49 4036.45,1681.49 4070.62,1715.66 4070.62,1725.64 4104.79,1759.81 4119.4,1759.81 v1(4142.09,1782.5)
  Bottom Layer w10: v1(1873.73,1873.42) 1982.16,1765 2007.49,1765 2022.04,1750.45 2053.79,1750.45 2081.54,1778.2 2101.94,1778.2 2135.64,1811.9 2189.76,1811.9 2222.99,1845.13 v1(2222.99,1865.96)
IMON_B: C202.1 J200.10 R204.2 U10.1 U200.14 | length 3942.4
  Top Layer w10: R204.2@1875.03,533.92 1874.04,533.92 1844.83,563.14 1844.83,632.73 1875.03,662.93 v1(1875.03,663.92) 1875.03,707.08 1896.37,728.43 U200.14@1896.37,762.83 ; U10.1@4105.51,1708.9 v1(4105.51,1730.12)
  Layer 2 w10: v1(2130,415) 2940,415 J200.10@3023,498 3023,552 2910,665 2910,1495 2930,1515 3740,1515 v1(3741.81,1513.19)
  Bottom Layer w10: v1(1875.03,663.92) 1875.03,605.65 2065.67,415 v1(2130,415) ; v1(3741.81,1513.19) 3744.45,1513.19 3900,1668.74 4042.31,1668.74 4103.69,1730.12 v1(4105.51,1730.12)
NetC0_1: C0.1 C1.1 C2.1 D1.2 J1.1 L1.1 TP1.1 | length 204.5
  Top Layer w10: D1.2@866.54,3194.32 D1.2@836.61,3224.24 L1.1@996.06,3194.32
NetC3_1: C3.1 C4.1 L1.4 Q1.1 Q1.2 Q1.3 U1.1 U1.5 | length 860.7
  Top Layer w10: L1.4@1181.1,3194.32 1280.09,3194.32 1287.82,3202.04 ; U1.1@1330.63,3044 1330.63,3063.32 1336.49,3069.18 1362.3,3069.18 ; C4.1@1406.5,2881.48 1406.5,2952.76 U1.5@1414.21,2960.47 ; U1.5@1417.32,2960.47 1415.12,2962.68 1386.19,2962.68 1367.64,2981.23 1367.64,3024.92 1362.3,3030.26 1362.3,3069.18 ; Q1.3@1421.7,3156.97 Q1.3@1426.62,3156.97 Q1.2@1426.62,3206.97 Q1.1@1426.62,3256.97 1341.76,3256.97 1332.26,3247.47 1332.26,3246.48 1287.82,3202.04 ; 1287.82,3202.04 1297.7,3202.04 1300.33,3199.41 1301.32,3199.41 1315.02,3185.71 1318.82,3189.51 1356.45,3189.51 1362.3,3183.65 1362.3,3069.18
NetC4_2: C4.2 U1.4 | length 92.3
  Top Layer w10: U1.4@1318.82,2956.61 1330.63,2956.61 1343.5,2943.74 C4.2@1343.5,2881.48
NetC9_2: C9.2 R1.1 | length 493.7
  Top Layer w10: C9.2@2694.18,2870.89 C9.2@2726.38,2903.09
  Top Layer w50: R1.1@2278.23,2869.57 C9.2@2726.38,2870.89
NetC20_1: C20.1 U10.26 | length 73.8
  Top Layer w10: U10.26@4249.21,1734.49 4249.21,1755.98 4256.97,1763.74 4257.95,1763.74 4285.8,1791.58 C20.1@4285.8,1792.57
NetC21_2: C21.2 R23.1 R24.2 U10.32 | length 470.5
  Top Layer w10: R23.1@3844.79,2019.24 3844.79,1957.31 R24.2@3848.57,1953.53 3848.57,1952.54 3862.27,1938.84 3863.26,1938.84 3931.86,1870.24 4041.1,1870.24 4075.49,1835.85 C21.2@4076.48,1835.85 4079.19,1833.13 4079.19,1802.11 4085.98,1795.32 4085.98,1786.34 4131.1,1741.22 U10.32@4131.1,1734.49 ; C21.2@4071.61,1822.11 C21.2@4073.58,1822.11
NetC101_1: C101.1 R101.1 R113.2 | length 132.3
  Top Layer w10: R113.2@1939.35,1708.08 C101.1@2003.27,1708.08 R101.1@2003.27,1774.23 R101.1@2003.27,1776.43
NetC110_1: C110.1 R106.1 | length 62.5
  Top Layer w10: R106.1@1568.57,1984.35 C110.1@1568.57,2046.84
NetC110_2: C110.2 U100.4 | length 127.9
  Top Layer w10: C110.2@1631.56,2046.84 1645.26,2060.54 1677.98,2060.54 1704.28,2086.84 U100.4@1742.83,2086.84 ; U100.4@1742.33,2086.54 U100.4@1742.41,2086.61
NetC111_1: C111.1 R107.1 U100.11 | length 176.7
  Top Layer w10: C111.1@1744.03,1878.56 1745.02,1878.56 1772.86,1906.41 1772.86,1923.24 1779.07,1929.46 1796.42,1929.46 1817.55,1950.59 1817.55,1962.75 U100.11@1817.63,1962.83 ; R107.1@1746.64,1822.07 C111.1@1746.64,1873.29
NetC111_2: C111.2 R108.1 U100.12 | length 172.5
  Top Layer w10: R108.1@1800.13,1813.44 1807.03,1820.34 C111.2@1807.03,1878.56 1807.12,1878.66 1807.12,1906.41 1856.58,1955.87 U100.12@1856.58,1962.6
NetC112_1: C112.1 L100.1 L101.1 U100.20 U100.21 U100.22 | length 109.1
  Top Layer w10: U100.22@1976.82,2145.67 C112.1@1991.54,2253.79
NetC112_2: C112.2 R109.1 | length 70.2
  Top Layer w10: C112.2@1973.07,2321.5 C112.2@1977.56,2317
  Top Layer w30: R109.1@1927.71,2316.78 C112.2@1991.54,2316.78
NetC141_1: C141.1 U140.3 | length 93.2
  Top Layer w10: U140.3@4444.96,2160.43 v1(4483.35,2160.43)
  Bottom Layer w10: v1(4483.35,2160.43) 4483.35,2130.55 4485.91,2127.99 4485.91,2127.01 4499.61,2113.31 C141.1@4500.59,2113.31
NetC201_1: C201.1 R201.1 R213.2 | length 129.5
  Top Layer w10: R213.2@1943.92,500.86 1943.92,501.85 1945.35,500.41 C201.1@2005.37,500.41 R201.1@2005.37,566.93
NetC210_1: C210.1 R206.1 | length 62.5
  Top Layer w10: R206.1@1565.11,787.05 C210.1@1565.11,849.54
NetC210_2: C210.2 U200.4 | length 132.1
  Top Layer w10: C210.2@1616.29,849.54 C210.2@1618.26,849.54 ; C210.2@1628.1,849.54 1641.8,863.24 1677.6,863.24 1701.2,886.84 U200.4@1742.83,886.84
NetC211_1: C211.1 R207.1 U200.11 | length 190.4
  Top Layer w10: R207.1@1738.51,611.41 1738.51,672.57 C211.1@1744.86,678.92 1745.84,678.92 1768.34,701.42 1768.34,710.96 1789.85,732.47 1799.43,732.47 1817.55,750.59 1817.55,762.75 U200.11@1817.63,762.83
NetC211_2: C211.2 R208.1 U200.12 | length 173.6
  Top Layer w10: R208.1@1803.55,611.41 1803.55,674.62 C211.2@1807.85,678.92 1807.85,706.94 1857,756.09 U200.12@1857,762.83
NetC212_1: C212.1 L200.1 L201.1 U200.20 U200.21 U200.22 | length 128.4
  Top Layer w10: U200.22@1977.08,945.98 1977.24,945.98 C212.1@1977.24,1054.35 ; U200.20@1977.24,906.53 U200.21@1977.24,926.21 ; C212.1@1990.02,1053.53 C212.1@1990.17,1053.37
NetC212_2: C212.2 R209.1 | length 65.5
  Top Layer w25: R209.1@1924.5,1115.52 C212.2@1990.02,1116.52
NetC241_1: C241.1 U240.3 | length 95.7
  Top Layer w10: U240.3@4444.96,960 v1@4482.5,960
  Bottom Layer w10: v1(4482.5,962) C241.1@4484.53,903.92
NetJ10_4: J10.4 R19.2 R20.1 U10.24 | length 406.2
  Top Layer w10: U10.24@4294.49,1708.9 4301.22,1708.9 4323.72,1731.4 4323.72,1755.06 4356.44,1787.77 R19.2@4356.44,1788.76 4413.56,1788.76 4425.16,1800.36 4425.16,1828.81 R20.1@4438.86,1842.51 4445.52,1835.85 J10.4@4611.52,1835.85
NetJ30_5: J30.5 R32.1 | length 172.3
  Top Layer w10: R32.1@3708.5,774.92 3720.31,763.11 J30.5@3720.31,607.5
NetL100_2: L100.2 L101.2 R107.2 R110.1 R111.1 | length 1069.9
  Top Layer w10: L101.2@2308.42,2162.94 2362.48,2108.89 2362.48,2095.73 2407.26,2050.95 v4(2407.26,2023.39) 2407.26,1942.92 2400.47,1936.13 R110.1@2399.48,1936.13
  Layer 2 w10: v1@1735.67,1750.45 1737.16,1751.94 1760.67,1751.94 1785.56,1776.82 1789.7,1776.82 1790.5,1777.63 1814.7,1777.63 1835.39,1798.32 1965.84,1798.32 2110,1943.77 2123.05,1943.77 2139.55,1960.27 2139.55,1982.24 2154.55,1997.24 2382.73,1997.24 v4(2407.26,2023.39)
  other v1: 1742.33,1751.94
NetL200_2: L200.2 L201.2 R207.2 R210.1 R211.1 | length 916.5
  Top Layer w10: R210.1@2392.52,735.25 v1(2407.44,823)
  Layer 2 w10: v1(1738.51,548.42) 1773.15,548.42 1787.05,562.33 1787.05,629.68 1869.87,712.5 1952.91,712.5 1965.41,725 2006.26,725 2033.01,751.75 2336.2,751.75 v1(2407.44,823) v1@2405.37,828
NetQ1_4: Q1.4 U1.6 | length 178.9
  Top Layer w10: U1.6@1421.18,2982.2 1390,2982.2 1384.14,2988.06 1384.14,3064.49 1411.94,3092.29 1411.94,3097.21 1421.7,3106.97 Q1.4@1426.62,3106.97
NetQ10_1: Q10.1 R25.2 R26.1 | length 174.2
  Top Layer w10: R25.2@3625.85,1922.03 3682.85,1922.03 3695,1909.88 Q10.1@3695,1902.49 3695,1830.57 3708.93,1816.64 R26.1@3709.91,1816.64
NetQ10_2: Q10.2 R24.1 | length 86.8
  Top Layer w10: Q10.2@3769.81,1902.49 3769.81,1897.28 3776.55,1890.54 R24.1@3848.57,1890.54
NetR13_1: R13.1 U10.15 | length 241
  Top Layer w10: U10.15@4249.21,1545.51 4249.29,1545.43 4249.29,1533.28 4272.58,1509.98 4321.01,1509.98 4321.49,1509.5 4422.84,1509.5 4425.16,1507.18 4425.16,1484.5 R13.1@4438.86,1470.8
NetR22_1: R22.1 U10.13 | length 138.2
  Top Layer w10: U10.13@4209.84,1545.51 4209.92,1545.43 4209.92,1527.76 v1(4221.29,1516.4) 4221.29,1514.7 4242.51,1493.48 4268.23,1493.48 4300.73,1460.98 R22.1@4300.73,1460
NetR106_2: R106.2 U100.5 | length 146.6
  Top Layer w10: R106.2@1631.56,1984.35 1632.55,1984.35 1674.24,2026.04 1674.24,2027.88 1698.92,2052.56 1700.28,2052.56 1714.88,2067.16 U100.5@1742.83,2067.16
NetR110_2: R110.2 R112.1 U100.13 | length 1207.3
  Top Layer w10: v1(1861.97,1927.17) 1876.26,1941.46 U100.13@1876.26,1962.6 ; R110.2@2400.47,1881.01 2392.52,1873.06 v1(2392.52,1869.63) R110.2@2392.52,1866.19 2403.9,1877.58 2403.9,1878.56 2406.22,1880.87 2462.24,1880.87 R112.1@2462.38,1881.01
  Layer 2 w10: v1(1861.97,1927.17) 1752.7,1817.89 1752.7,1814.82 1716.08,1778.2 1716.08,1721.82 1721.93,1715.96 1832.62,1715.96 1871.98,1755.32 1981.26,1755.32 2018.46,1792.51 2018.46,1796.16 2084.01,1861.72 2087.66,1861.72 2153.22,1927.27 2262.4,1927.27 2277.93,1911.75 2376.25,1911.75 v1@2392.52,1867.91
NetR206_2: R206.2 U200.5 | length 147.9
  Top Layer w10: R206.2@1628.1,787.05 1629.09,787.05 1709.19,867.16 U200.5@1742.83,867.16
NetR210_2: R210.2 R212.1 U200.13 | length 634.5
  Top Layer w10: v1(1871.54,734) 1876.68,739.15 U200.13@1876.68,762.83
  Top Layer w20: v1(2385,669.97) R212.1@2447.81,668.48
  Layer 2 w10: v1@2384.45,670.52 v1(2385,669.97)
  Bottom Layer w10: v1(1871.54,734) 1900.12,734 1944.12,690 2102.97,690 2123,669.97 v1(2385,669.97)
NetTP10_1: TP10.1 U10.18 | length 159.1
  Top Layer w10: U10.18@4294.57,1590.71 U10.18@4294.49,1590.79 4336.36,1590.79 4348.46,1578.69 4441.35,1578.69 TP10.1@4446.35,1573.69
NetTP11_1: TP11.1 U10.17 | length 102.2
  Top Layer w10: U10.17@4294.49,1571.1 4301.22,1571.1 4319.82,1552.5 4381.96,1552.5 TP11.1@4386.96,1547.5
NetTP12_1: TP12.1 U10.25 | length 222.5
  Top Layer w10: U10.25@4268.9,1734.49 4268.9,1739.92 4268.98,1740 4285.55,1740 4285.55,1744.23 4291.81,1750.48 v1(4291.81,1753.19)
  Layer 2 w10: v1(4291.81,1753.19) 4310.79,1772.17 4447.11,1772.17 4450.99,1768.29 4464.21,1768.29 v1(4466.12,1766.38)
nINT-DCDCs: J100.8 J200.8 R12.2 R13.2 U100.16 U200.16 | length 5205.8
  Top Layer w10: U100.16@1935.32,1962.6 1935.4,1962.52 1935.4,1945.54 1944.18,1936.76 v1(1944.18,1934.06) ; U200.16@1935.74,762.83 1935.82,762.75 1935.82,744.89 1944,736.71 v1(1944,734) ; v1(4368.59,1472.48) R12.2@4368.59,1471.5 4368.59,1470.51 4404.61,1434.5 4413.16,1434.5 4438.86,1408.79 R13.2@4438.86,1407.81
  Layer 2 w10: v1(1944,734) 1946.71,734 1959.78,747.08 2005,747.08 2057.92,800 2354.04,800 2398.54,844.5 2474.5,844.5 2509.5,809.5 2509.5,689.5 2624,575 2746,575 J200.8@2823,498 v1(2822.99,1515) ; v1(2085.5,1809.01) 2712.16,1809.01 J100.8@2822.99,1698.19 2881.18,1640 3791,1640 3905,1526 3905,1456.41 3979.85,1456.41 3991.54,1444.72 3991.54,1430.86 3997.4,1425 4265.71,1425 4313.19,1472.48 v1(4368.59,1472.48)
  Bottom Layer w10: v1(1944.18,1934.06) 1946.09,1932.14 1962.37,1932.14 v1(2085.5,1809.01) ; v1(2822.99,1515) J100.8@2822.99,1698.19
PA_SYNC: J100.2 U10.21 U100.8 | length 3690.3
  Top Layer w10: v1(1727.99,1934.06) 1727.99,1936.76 1742.41,1951.18 1742.41,1988.19 U100.8@1735.67,1988.19 ; U10.21@4294.49,1649.84 4323.72,1649.84 4326.32,1647.24 4365.34,1647.24 4368.59,1650.49 v1(4371.29,1650.49)
  Layer 2 w10: v1(1727.99,1934.06) 1673,1879.07 1673,1693.86 1678.86,1688 1704.45,1688 1704.96,1688.51 2056.9,1688.51 2071.89,1703.5 2071.89,1727.17 2086.89,1742.17 2179.01,1742.17 J100.2@2222.99,1698.19 2266.97,1742.17 2462.83,1742.17 2475,1730 2475,1670 2515,1630 2867.84,1630 2882.64,1615.2 3780,1615.2 3885,1510.2 3885,1427.52 3912.52,1400 3936.67,1400 3945.17,1391.5 4297.26,1391.5 4314.26,1408.5 4315.59,1408.5 4355.29,1448.2 4391.48,1448.2 4399.69,1456.41 4399.69,1522.61 4349.79,1572.5 4349.79,1628.99 v1(4371.29,1650.49)
PB_SYNC: J200.2 U10.16 U200.8 | length 3966
  Top Layer w10: v1(1738.89,735.25) 1738.89,788.34 1738.97,788.42 U200.8@1742.83,788.42 ; U10.16@4268.98,1545.43 U10.16@4268.9,1545.51 4268.9,1538.78 4268.98,1538.7 4275.71,1538.7 4283.41,1531 v1(4330.39,1531)
  Layer 2 w10: v1(1738.89,735.25) 1738.89,626.52 1714.28,601.91 1714.28,514.7 1730.98,498.01 1923.01,498.01 1980,555 2195,555 2202.07,547.93 2202.07,533.8 2223,512.87 J200.2@2223,498
  Bottom Layer w10: J200.2@2223,498 2347.5,622.5 2417.14,622.5 2423,628.36 2423,728.67 2347.5,804.17 2347.5,1167.5 2370,1190 2370,1201.63 2493.37,1325 4230.39,1325 4330.39,1425 v1(4330.39,1531)
TEMP_A: C13.1 R16.1 R105.1 U10.11 | length 2767.4
  Top Layer w10: v1(4169.29,1465.99) 4170.45,1467.15 4170.45,1502.07 4172.29,1503.91 4172.29,1525.3 4170.55,1527.04 4170.55,1545.43 U10.11@4170.47,1545.51
  Bottom Layer w10: R105.1@1938.86,2086.06 1938.86,2028.46 2047.38,1919.94 2110.97,1919.94 2118.3,1927.27 2241.23,1927.27 2341.69,1826.82 3170,1826.82 3220,1776.82 3220,1710.32 3221.5,1708.82 3221.5,1642.32 3220,1640.82 3456.26,1404.56 3785.72,1404.56 3837.57,1456.41 4080,1456.41 4087.07,1463.48 4087.07,1474.59 4103.15,1490.67 4116.85,1490.67 4123.7,1483.82 4151.46,1483.82 v1(4169.29,1465.99)
TEMP_B: C14.1 R21.1 R205.1 U10.12 | length 2733.9
  Top Layer w10: U10.12@4190.16,1545.51 4190.16,1517.18 4199.79,1507.55 4199.79,1488.38 v1(4230.77,1456.41)
  Bottom Layer w10: R205.1@1939.13,886 1944.45,886 2430,1350 3275,1350 3315,1390 3362.35,1390 3368.21,1384.14 3368.21,1377.24 3389.71,1355.74 3761.07,1355.74 3772.68,1367.35 3772.68,1368.18 3838.99,1434.5 3841.84,1434.5 3847.26,1439.91 4214.27,1439.91 v1(4230.77,1456.41) 4256.8,1493 C14.1@4285.51,1493
V_Batt_Protected: C5.1 C6.1 C7.1 C8.1 L2.1 Q1.5-6
VBUS_A: C113.1 C114.1 C115.1 C116.1 C117.1 C118.1 C119.1 C130.1 C131.1 J100.7 J130.A4 J130.A9 J130.B4 J130.B9 R10.2 R108.2 R111.2 R112.2 TP100.1 | length 1842.1
  Top Layer w10: R112.2@2462.38,1936.13 v1(2462.38,2023.39) ; J100.7@2722.99,1698.19 2722.99,1712.83 2759.73,1749.57 2759.73,2036.12 2758.64,2037.21 2758.64,2045.5 2759.69,2046.55 2759.69,2056.54 2727.9,2056.54 v1(2722.99,2061.45) ; C130.1@4507.11,2415.03 4506.13,2415.03 4492.43,2401.33 4492.43,2400.35 4473.5,2381.42 4473.5,2350.59 C131.1@4452.91,2330 4452.91,2319.17 4473.5,2298.58 4509.95,2298.58 4587.23,2221.3 4588.91,2221.3 4611.07,2199.13 J130.A9@4652.36,2199.13 J130.A9@4652.36,2199.13 4684.09,2199.06 4690.59,2192.56 4700.44,2192.56 4703.7,2189.29 J130.B4@4715.35,2189.29 ; 4620.63,2100.71 J130.A4@4652.36,2100.71 4652.44,2100.63 4673.86,2100.63 4683.62,2090.87 J130.B9@4715.35,2090.87
  Layer 2 w10: v1(1800.13,1750.45) 1802.04,1752.36 1819.84,1752.36 1844.29,1776.82 1970,1776.82 2122.99,1927.17 2129.78,1927.17 2146.38,1943.77 2355.28,1943.77 2360.86,1938.2 2369.14,1938.2 2382.56,1951.62 2390.61,1951.62 v1(2462.38,2023.39)
  Bottom Layer w10: v1(2722.99,2061.45) 2723.13,2061.45 C116.1@2743.23,2041.35
  other v1: 2669,2060.65 2527.83,2067.99 2586.81,2067.99
VBUS_A_LV: C10.1 R10.1 R11.1 U10.30 | length 381.2
  Top Layer w10: R10.1@4103.78,2032.4 4103.78,1965.09 4077.56,1938.87 4077.56,1890 4116.93,1890 4129.53,1877.4 4129.53,1814.88 4135.39,1809.02 4153.99,1809.02 4170.47,1792.54 U10.30@4170.47,1734.49
VBUS_B: C213.1 C214.1 C215.1 C216.1 C217.1 C218.1 C219.1 C230.1 C231.1 J200.7 J230.A4 J230.A9 J230.B4 J230.B9 R14.2 R208.2 R211.2 R212.2 TP200.1 | length 3127.1
  Top Layer w10: R212.2@2460.5,735.25 2460.5,820.94 v1(2461.53,821.97) R211.2@2462.56,823 ; J200.7@2723,498 2723,501.85 2754.65,533.5 2754.65,825.05 2754.19,825.5 2754.19,844.54 2756.5,846.84 ; R14.2@3969.31,1262.51 R14.2@3976.81,1270.02 3976.81,1144.98 ; C231.1@4444.36,1138.56 C231.1@4452.91,1130 C231.1@4452.91,1119.17 ; 4569.06,895.04 4603.28,895.04 4608.95,900.71 J230.A4@4652.36,900.71 4682.33,900.71 4692.09,890.94 4715.28,890.94 J230.B9@4715.35,890.87 ; 4571.25,1002.5 4574.61,999.13 ; 4622.83,998.19 4623.78,999.13 J230.A9@4652.36,999.13 J230.A9@4652.36,999.13 4669.52,999.06 4679.28,989.29 J230.B4@4715.35,989.29
  Top Layer w20: 4574.61,999.13 4622.83,998.19
  Top Layer w40: C231.1@4444.36,1138.56 4072.48,1138.56 4017.17,1083.24 4017.17,1034 4060.25,990.92 4060.25,864.1 4083.68,840.67 4509.03,840.67 4563.4,895.04 4569.06,895.04 ; C231.1@4452.91,1119.17 4535.21,1036.87 4543.09,1036.87 4571.25,1008.71 4571.25,1002.5
  Layer 2 w10: v1(1803.55,548.42) 1803.55,622.85 1866.12,685.42 1875.03,685.42 1881.61,692 1955.74,692 1972.24,708.5 2036.01,708.5 2062.76,735.25 2352.25,735.25 2440,823 2460.5,823 v1(2461.53,821.97)
  other v1: 2665.47,860.83 2722.99,861.11 2535,865.09 2583.4,865.09
VBUS_B_LV: C11.1 R14.1 R15.1 U10.9 | length 314.3
  Top Layer w10: C11.1@4026.29,1426.46 4026.29,1425.48 C11.1@4030.23,1425.48 4031.21,1425.48 4065.66,1459.93 4065.66,1473.34 4131.1,1538.78 U10.9@4131.1,1545.51 ; C11.1@4037.04,1414.73 4037.04,1383.36 4041.18,1379.22 R15.1@4041.18,1345.52 4039.8,1344.14 R14.1@4039.8,1270.02
VCC_A: C103.1 J100.9 U100.19 | length 1120
  Top Layer w10: U100.19@1970.75,2047.24 2039.01,2047.24 2110.52,1975.74 C103.1@2111.5,1975.74 2112.49,1975.74 2162.09,1926.13 2162.09,1916.67 v1(2172.99,1905.77) ; J100.9@2922.99,1698.19 J100.9@2925.21,1695.97
  Layer 2 w10: v1(2172.99,1905.77) 2172.99,1881.01 2225.38,1828.63 2265,1828.63 2266.81,1826.82 2794.36,1826.82 J100.9@2922.99,1698.19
